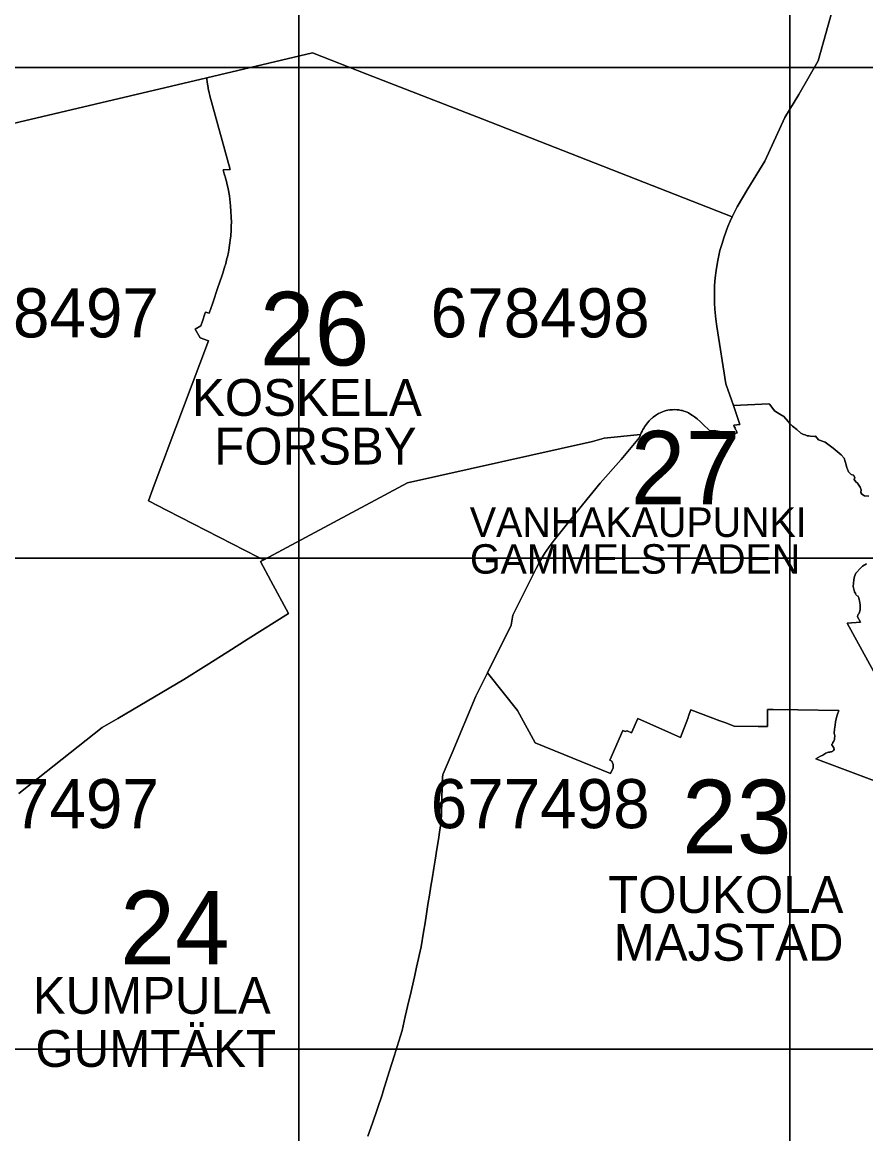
# Model space of a CAD drawing. Extents: x 25485000 to 25520000, y 6656775 to 6690000.
# Drawn here: x 25497436 to 25499155, y 6676827 to 6679092 of the extents above; entities that cross this region are included whole.
import ezdxf

# ---------------------------------------------------------------- set-up
doc = ezdxf.new("R2010")
doc.units = 0
doc.layers.add('Level 63', color=7, linetype='Continuous')

msp = doc.modelspace()

# ---------------------------------------------------------------- linework, layer by layer
at = {"layer": 'Level 63'}
for points in [[(25497000, 6679000), (25498000, 6679000), (25498000, 6680000), (25497000, 6680000)], [(25498000, 6679000), (25499000, 6679000), (25499000, 6680000), (25498000, 6680000)], [(25499000, 6679000), (25500000, 6679000), (25500000, 6680000), (25499000, 6680000)], [(25497693.2, 6678117), (25497731.3, 6678097.5), (25497917.1, 6678002.3), (25497928.4, 6677996.5), (25498221.5, 6678153.3), (25498598.3, 6678238), (25498621.9, 6678244.4), (25498696, 6678251.9), (25498697.5, 6678255.3), (25498699.1, 6678258.6), (25498701, 6678262.2), (25498703.2, 6678265.8), (25498704.5, 6678267.8), (25498706.4, 6678270.6), (25498710.5, 6678276), (25498714, 6678279.9), (25498716, 6678282.1), (25498718.5, 6678284.5), (25498719.8, 6678285.6), (25498722, 6678287.6), (25498726.3, 6678290.7), (25498728.4, 6678292.1), (25498730.6, 6678293.4), (25498732.8, 6678294.7), (25498736, 6678296.3), (25498740.7, 6678298.3), (25498744.2, 6678299.5), (25498748.2, 6678300.7), (25498751.5, 6678301.4), (25498755.9, 6678302.2), (25498761.3, 6678302.7), (25498766.1, 6678302.8), (25498770.8, 6678302.5), (25498774, 6678302.2), (25498776.5, 6678301.8), (25498779.8, 6678301.2), (25498781.6, 6678300.7), (25498784.5, 6678299.9), (25498787.3, 6678298.9), (25498790.9, 6678297.5), (25498793.8, 6678296), (25498796.7, 6678294.3), (25498801.7, 6678291), (25498806.2, 6678288), (25498811.4, 6678283.9), (25498818.2, 6678278), (25498823.1, 6678273.4), (25498837.2, 6678259.3), (25498846.1, 6678260.1), (25498857.3, 6678258), (25498873.7, 6678255), (25498887.6, 6678253.2), (25498893.2, 6678255.4), (25498892.3, 6678257.1), (25498891.8, 6678259.4), (25498891, 6678261.1), (25498889.5, 6678262.5), (25498888.8, 6678263.8), (25498889.3, 6678264.1), (25498887.1, 6678268.7), (25498886.4, 6678271), (25498898.3, 6678272.2), (25498885.2, 6678311), (25498870.2, 6678355.4), (25498851.7, 6678472.3), (25498849.6, 6678487.1), (25498847.5, 6678507.4), (25498846.9, 6678519.5), (25498846.5, 6678531.5), (25498846.7, 6678543.5), (25498847.1, 6678555.4), (25498848.3, 6678571), (25498849.9, 6678586.4), (25498852.1, 6678599.2), (25498853.4, 6678606.8), (25498857.9, 6678626.8), (25498862.1, 6678641.6), (25498865.7, 6678653.1), (25498869.9, 6678664.4), (25498874.1, 6678675.6), (25498878.9, 6678686.7), (25498883.1, 6678695.6), (25498374.4, 6678894.4), (25498138.3, 6678986.6), (25498027.5, 6679029.9), (25497812.2, 6678979.1), (25497812.4, 6678976.1), (25497813, 6678970.5), (25497813.5, 6678966.2), (25497814.2, 6678962.2), (25497814.7, 6678959.4), (25497814.9, 6678957.8), (25497815.2, 6678956.4), (25497815.2, 6678956.3), (25497815.3, 6678956), (25497815.4, 6678955.3), (25497815.7, 6678954), (25497816.8, 6678949), (25497817.8, 6678945.1), (25497818.2, 6678943.7), (25497818.6, 6678942.2), (25497860, 6678792.2), (25497845.3, 6678791.1), (25497847, 6678785.9), (25497847.9, 6678783), (25497848.6, 6678780.9), (25497849.1, 6678778.9), (25497849.5, 6678777.7), (25497850.3, 6678774.7), (25497851.5, 6678770.2), (25497853.1, 6678764), (25497855.7, 6678752.5), (25497858.2, 6678738.6), (25497860.8, 6678718.3), (25497862.3, 6678683.8), (25497862.2, 6678677.8), (25497861.8, 6678668.2), (25497861, 6678656.9), (25497860, 6678647.9), (25497859.4, 6678642.7), (25497858.7, 6678637.6), (25497857, 6678627.9), (25497856.2, 6678623.5), (25497854.2, 6678613.9), (25497853.4, 6678610.6), (25497851.8, 6678603.9), (25497850.2, 6678598), (25497849.3, 6678595.1), (25497844.8, 6678580.6), (25497842.9, 6678575), (25497834.9, 6678551.3), (25497832.8, 6678545.2), (25497826.5, 6678526.7), (25497823.6, 6678518.1), (25497817.2, 6678499.2), (25497809.6, 6678501.7), (25497808.3, 6678498), (25497803.2, 6678482.8), (25497800, 6678473.4), (25497788.7, 6678466.6), (25497798.9, 6678449.4), (25497815.4, 6678443.2), (25497731.6, 6678219.4), (25497728.1, 6678210.1), (25497717.5, 6678181.7), (25497702.3, 6678141.3)], [(25497000, 6678000), (25498000, 6678000), (25498000, 6679000), (25497000, 6679000)], [(25498000, 6678000), (25499000, 6678000), (25499000, 6679000), (25498000, 6679000)], [(25499000, 6678000), (25500000, 6678000), (25500000, 6679000), (25499000, 6679000)], [(25497000, 6677000), (25498000, 6677000), (25498000, 6678000), (25497000, 6678000)], [(25498000, 6677000), (25499000, 6677000), (25499000, 6678000), (25498000, 6678000)], [(25499000, 6677000), (25500000, 6677000), (25500000, 6678000), (25499000, 6678000)], [(25497000, 6676000), (25498000, 6676000), (25498000, 6677000), (25497000, 6677000)], [(25498000, 6676000), (25499000, 6676000), (25499000, 6677000), (25498000, 6677000)], [(25499000, 6676000), (25500000, 6676000), (25500000, 6677000), (25499000, 6677000)]]:
    msp.add_lwpolyline(points, close=True, dxfattribs=at)
for points in [[(25497201, 6678835), (25497812.2, 6678979.1), (25498027.5, 6679029.9), (25498138.3, 6678986.6), (25498374.4, 6678894.4), (25498883.1, 6678695.6), (25498893.3, 6678715.7), (25498914.4, 6678752.7), (25498949.4, 6678808.9), (25498990.1, 6678898.1), (25499018.9, 6678944.9), (25499058.2, 6679013.5), (25499094, 6679142.7)], [(25499094, 6679142.7), (25499058.2, 6679013.5), (25499018.9, 6678944.9), (25498990.1, 6678898.1), (25498949.4, 6678808.9), (25498914.4, 6678752.7), (25498893.3, 6678715.7), (25498883.1, 6678695.6), (25498878.9, 6678686.7), (25498874.1, 6678675.6), (25498869.9, 6678664.4), (25498865.7, 6678653.1), (25498862.1, 6678641.6), (25498857.9, 6678626.8), (25498853.4, 6678606.8), (25498852.1, 6678599.2)], [(25497429.3, 6677520.9), (25497468.6, 6677551.9), (25497599.2, 6677655.1), (25497631.3, 6677673.2), (25497765.3, 6677752.8), (25497811, 6677781.6), (25497855, 6677809.3), (25497896.5, 6677835.5), (25497978.6, 6677887.3), (25497942.8, 6677954.3), (25497922, 6677993.1), (25497928.4, 6677996.5), (25497917.1, 6678002.3), (25497731.3, 6678097.5), (25497693.2, 6678117), (25497702.3, 6678141.3), (25497717.5, 6678181.7), (25497728.1, 6678210.1), (25497731.6, 6678219.4), (25497815.4, 6678443.2), (25497798.9, 6678449.4), (25497788.7, 6678466.6), (25497800, 6678473.4), (25497803.2, 6678482.8), (25497808.3, 6678498), (25497809.6, 6678501.7), (25497817.2, 6678499.2), (25497823.6, 6678518.1), (25497826.5, 6678526.7), (25497832.8, 6678545.2), (25497834.9, 6678551.3), (25497842.9, 6678575), (25497844.8, 6678580.6), (25497849.3, 6678595.1), (25497850.2, 6678598), (25497851.8, 6678603.9), (25497853.4, 6678610.6), (25497854.2, 6678613.9), (25497856.2, 6678623.5), (25497857, 6678627.9), (25497858.7, 6678637.6), (25497859.4, 6678642.7), (25497860, 6678647.9), (25497861, 6678656.9), (25497861.8, 6678668.2), (25497862.2, 6678677.8), (25497862.3, 6678683.8), (25497860.8, 6678718.3), (25497858.2, 6678738.6), (25497855.7, 6678752.5), (25497853.1, 6678764), (25497851.5, 6678770.2), (25497850.3, 6678774.7), (25497849.5, 6678777.7), (25497849.1, 6678778.9), (25497848.6, 6678780.9), (25497847.9, 6678783), (25497847, 6678785.9), (25497845.3, 6678791.1), (25497860, 6678792.2), (25497818.6, 6678942.2), (25497818.2, 6678943.7), (25497817.8, 6678945.1), (25497816.8, 6678949), (25497815.7, 6678954), (25497815.4, 6678955.3), (25497815.3, 6678956), (25497815.2, 6678956.3), (25497815.2, 6678956.4), (25497814.9, 6678957.8), (25497814.7, 6678959.4), (25497814.2, 6678962.2), (25497813.5, 6678966.2), (25497813, 6678970.5), (25497812.4, 6678976.1), (25497812.2, 6678979.1), (25497201, 6678835)], [(25498852.1, 6678599.2), (25498849.9, 6678586.4), (25498848.3, 6678571), (25498847.1, 6678555.4), (25498846.7, 6678543.5), (25498846.5, 6678531.5), (25498846.9, 6678519.5), (25498847.5, 6678507.4), (25498849.6, 6678487.1), (25498851.7, 6678472.3), (25498870.2, 6678355.4), (25498885.2, 6678311), (25498957.2, 6678314.4), (25498959.6, 6678313.1), (25498969, 6678300.2), (25498979.6, 6678293.7), (25498988, 6678288.9), (25498996.7, 6678278.6), (25499000.4, 6678274.7), (25499005.5, 6678268.8), (25499014.3, 6678262.3), (25499023, 6678254.5), (25499028.4, 6678251.9), (25499031.6, 6678251.7), (25499035.7, 6678249.7), (25499038.9, 6678249.6), (25499042.4, 6678248.6), (25499050.5, 6678248), (25499052.9, 6678248.4), (25499058.9, 6678241.2), (25499072.3, 6678236.7), (25499088.3, 6678224), (25499104.6, 6678210.8), (25499111.2, 6678203.8), (25499115.3, 6678190.3), (25499116.4, 6678184.1), (25499117.7, 6678181.8), (25499119.6, 6678176.1), (25499125.6, 6678170.4), (25499130.3, 6678169.2), (25499132.7, 6678164.2), (25499131.1, 6678160.7), (25499134.6, 6678155.7), (25499138.1, 6678152.9), (25499143.9, 6678144.7), (25499145.5, 6678139.5), (25499145.2, 6678134), (25499147, 6678130.7), (25499152.8, 6678127.3), (25499161.5, 6678126.3)], [(25499161.5, 6678126.3), (25499152.8, 6678127.3), (25499147, 6678130.7), (25499145.2, 6678134), (25499145.5, 6678139.5), (25499143.9, 6678144.7), (25499138.1, 6678152.9), (25499134.6, 6678155.7), (25499131.1, 6678160.7), (25499132.7, 6678164.2), (25499130.3, 6678169.2), (25499125.6, 6678170.4), (25499119.6, 6678176.1), (25499117.7, 6678181.8), (25499116.4, 6678184.1), (25499115.3, 6678190.3), (25499111.2, 6678203.8), (25499104.6, 6678210.8), (25499088.3, 6678224), (25499072.3, 6678236.7), (25499058.9, 6678241.2), (25499052.9, 6678248.4), (25499050.5, 6678248), (25499042.4, 6678248.6), (25499038.9, 6678249.6), (25499035.7, 6678249.7), (25499031.6, 6678251.7), (25499028.4, 6678251.9), (25499023, 6678254.5), (25499014.3, 6678262.3), (25499005.5, 6678268.8), (25499000.4, 6678274.7), (25498996.7, 6678278.6), (25498988, 6678288.9), (25498979.6, 6678293.7), (25498969, 6678300.2), (25498959.6, 6678313.1), (25498957.2, 6678314.4), (25498885.2, 6678311), (25498898.3, 6678272.2), (25498886.4, 6678271), (25498887.1, 6678268.7), (25498889.3, 6678264.1), (25498888.8, 6678263.8), (25498889.5, 6678262.5), (25498891, 6678261.1), (25498891.8, 6678259.4), (25498892.3, 6678257.1), (25498893.2, 6678255.4), (25498887.6, 6678253.2), (25498873.7, 6678255), (25498857.3, 6678258), (25498846.1, 6678260.1), (25498837.2, 6678259.3), (25498823.1, 6678273.4), (25498818.2, 6678278), (25498811.4, 6678283.9), (25498806.2, 6678288), (25498801.7, 6678291), (25498796.7, 6678294.3), (25498793.8, 6678296), (25498790.9, 6678297.5), (25498787.3, 6678298.9), (25498784.5, 6678299.9), (25498781.6, 6678300.7), (25498779.8, 6678301.2), (25498776.5, 6678301.8), (25498774, 6678302.2), (25498770.8, 6678302.5), (25498766.1, 6678302.8), (25498761.3, 6678302.7), (25498755.9, 6678302.2), (25498751.5, 6678301.4), (25498748.2, 6678300.7), (25498744.2, 6678299.5), (25498740.7, 6678298.3), (25498736, 6678296.3), (25498732.8, 6678294.7), (25498730.6, 6678293.4), (25498728.4, 6678292.1), (25498726.3, 6678290.7), (25498722, 6678287.6), (25498719.8, 6678285.6), (25498718.5, 6678284.5), (25498716, 6678282.1), (25498714, 6678279.9), (25498710.5, 6678276), (25498706.4, 6678270.6), (25498704.5, 6678267.8), (25498703.2, 6678265.8), (25498701, 6678262.2), (25498699.1, 6678258.6), (25498697.5, 6678255.3), (25498696, 6678251.9), (25498693.8, 6678245.9), (25498656.8, 6678200.9), (25498613.5, 6678153), (25498578.1, 6678108.9), (25498520.4, 6678037), (25498515.9, 6678031.1), (25498509.8, 6678023.2), (25498503.8, 6678014.5), (25498501.7, 6678011.4), (25498490.8, 6677993.4), (25498483.3, 6677979.1), (25498436.2, 6677884.3), (25498432.7, 6677863.9), (25498384.1, 6677766.3), (25498445.5, 6677689.6), (25498481.4, 6677624.1), (25498634.8, 6677561.2), (25498640, 6677573.3), (25498640.1, 6677579.8), (25498637.8, 6677586.5), (25498633.8, 6677588.3), (25498660.2, 6677648.8), (25498664.8, 6677646.8), (25498668.7, 6677648.4), (25498677.8, 6677644.4), (25498690.4, 6677673.2), (25498759.4, 6677643.1), (25498777.7, 6677635.1), (25498792.2, 6677673.4), (25498794.6, 6677680), (25498797.5, 6677687.5), (25498798.9, 6677691.2), (25498857.8, 6677669), (25498868.1, 6677665.1), (25498887.1, 6677658), (25498935.7, 6677657.4), (25498943.7, 6677657.4), (25498954.7, 6677657.2), (25498955.1, 6677691.7), (25498960.1, 6677691.7), (25498966.1, 6677691.6), (25499016.7, 6677691), (25499099.9, 6677690.1), (25499096.6, 6677680.6), (25499095.6, 6677675.4), (25499093.3, 6677666.7), (25499092.8, 6677659.7), (25499091.3, 6677651.7), (25499090.8, 6677643.6), (25499091.8, 6677638.5), (25499091.6, 6677633), (25499091.2, 6677630.6), (25499090, 6677627.5), (25499088.2, 6677624.4), (25499087.6, 6677623.2), (25499086.2, 6677621.2), (25499086.2, 6677619.8), (25499088.5, 6677615.5), (25499089.9, 6677613.6), (25499090.8, 6677610.6), (25499089.5, 6677608), (25499087.9, 6677606.6), (25499085.3, 6677605.4), (25499083.5, 6677605.3), (25499081.5, 6677604.8), (25499078.9, 6677604.8), (25499076.9, 6677604.4), (25499073.6, 6677602.8), (25499067.4, 6677599), (25499062.7, 6677596.8), (25499053.2, 6677591.3), (25499324.7, 6677489.2)], [(25498140.1, 6676822.7), (25498149.9, 6676849), (25498169.4, 6676906.6), (25498171.8, 6676914.2), (25498183.9, 6676953.3), (25498194.5, 6676987.6), (25498196.7, 6676994.5), (25498210.2, 6677038.1), (25498216.6, 6677066.2), (25498224, 6677098.4), (25498226.5, 6677108.7), (25498235.2, 6677147.4), (25498239.7, 6677166.9), (25498249.2, 6677208.4), (25498253.9, 6677238.2), (25498256.9, 6677256.9), (25498259.9, 6677275.7), (25498262.9, 6677294.4), (25498266, 6677313.2), (25498269, 6677332), (25498271.3, 6677346.8), (25498274.9, 6677368.8), (25498277.5, 6677385.1), (25498281, 6677407.1), (25498284.2, 6677426.8), (25498287.3, 6677446.6), (25498289.7, 6677461.3), (25498291, 6677503.7), (25498292.1, 6677540.9), (25498292.5, 6677553.7), (25498292.6, 6677555.4), (25498292.9, 6677557.2), (25498293.4, 6677559.1), (25498294.1, 6677560.9), (25498312.1, 6677603.7), (25498360.7, 6677719.2), (25498384.1, 6677766.3), (25498432.7, 6677863.9), (25498436.2, 6677884.3), (25498483.3, 6677979.1), (25498490.8, 6677993.4), (25498501.7, 6678011.4), (25498503.8, 6678014.5), (25498509.8, 6678023.2), (25498515.9, 6678031.1), (25498520.4, 6678037), (25498578.1, 6678108.9), (25498613.5, 6678153), (25498656.8, 6678200.9), (25498693.8, 6678245.9), (25498696, 6678251.9), (25498621.9, 6678244.4), (25498598.3, 6678238), (25498221.5, 6678153.3), (25497928.4, 6677996.5), (25497922, 6677993.1), (25497942.8, 6677954.3), (25497978.6, 6677887.3), (25497896.5, 6677835.5), (25497855, 6677809.3), (25497811, 6677781.6), (25497765.3, 6677752.8), (25497631.3, 6677673.2), (25497599.2, 6677655.1), (25497468.6, 6677551.9), (25497429.3, 6677520.9)], [(25499231.7, 6677658.5), (25499116.9, 6677867.7), (25499144.1, 6677869.8), (25499138, 6677880.7), (25499139, 6677884.5), (25499140.7, 6677886.9), (25499142.1, 6677890), (25499143.3, 6677894.6), (25499143.5, 6677905), (25499142.9, 6677909.1), (25499142, 6677912.9), (25499141.5, 6677916.2), (25499140.9, 6677919.6), (25499139.8, 6677922), (25499138.7, 6677923.4), (25499138, 6677922.9), (25499134.1, 6677927.1), (25499134.5, 6677927.8), (25499132, 6677931.6), (25499129.2, 6677942.3), (25499130.6, 6677956.2), (25499132.3, 6677962.8), (25499134.9, 6677969.6), (25499144.9, 6677980.7), (25499148.5, 6677983.6), (25499156.8, 6677988.8)], [(25499156.8, 6677988.8), (25499148.5, 6677983.6), (25499144.9, 6677980.7), (25499134.9, 6677969.6), (25499132.3, 6677962.8), (25499130.6, 6677956.2), (25499129.2, 6677942.3), (25499132, 6677931.6), (25499134.5, 6677927.8), (25499134.1, 6677927.1), (25499138, 6677922.9), (25499138.7, 6677923.4), (25499139.8, 6677922), (25499140.9, 6677919.6), (25499141.5, 6677916.2), (25499142, 6677912.9), (25499142.9, 6677909.1), (25499143.5, 6677905), (25499143.3, 6677894.6), (25499142.1, 6677890), (25499140.7, 6677886.9), (25499139, 6677884.5), (25499138, 6677880.7), (25499144.1, 6677869.8), (25499116.9, 6677867.7), (25499231.7, 6677658.5)], [(25499324.7, 6677489.2), (25499053.2, 6677591.3), (25499062.7, 6677596.8), (25499067.4, 6677599), (25499073.6, 6677602.8), (25499076.9, 6677604.4), (25499078.9, 6677604.8), (25499081.5, 6677604.8), (25499083.5, 6677605.3), (25499085.3, 6677605.4), (25499087.9, 6677606.6), (25499089.5, 6677608), (25499090.8, 6677610.6), (25499089.9, 6677613.6), (25499088.5, 6677615.5), (25499086.2, 6677619.8), (25499086.2, 6677621.2), (25499087.6, 6677623.2), (25499088.2, 6677624.4), (25499090, 6677627.5), (25499091.2, 6677630.6), (25499091.6, 6677633), (25499091.8, 6677638.5), (25499090.8, 6677643.6), (25499091.3, 6677651.7), (25499092.8, 6677659.7), (25499093.3, 6677666.7), (25499095.6, 6677675.4), (25499096.6, 6677680.6), (25499099.9, 6677690.1), (25499016.7, 6677691), (25498966.1, 6677691.6), (25498960.1, 6677691.7), (25498955.1, 6677691.7), (25498954.7, 6677657.2), (25498943.7, 6677657.4), (25498935.7, 6677657.4), (25498887.1, 6677658), (25498868.1, 6677665.1), (25498857.8, 6677669), (25498798.9, 6677691.2), (25498797.5, 6677687.5), (25498794.6, 6677680), (25498792.2, 6677673.4), (25498777.7, 6677635.1), (25498759.4, 6677643.1), (25498690.4, 6677673.2), (25498677.8, 6677644.4), (25498668.7, 6677648.4), (25498664.8, 6677646.8), (25498660.2, 6677648.8), (25498633.8, 6677588.3), (25498637.8, 6677586.5), (25498640.1, 6677579.8), (25498640, 6677573.3), (25498634.8, 6677561.2), (25498481.4, 6677624.1), (25498445.5, 6677689.6), (25498384.1, 6677766.3), (25498360.7, 6677719.2), (25498312.1, 6677603.7), (25498294.1, 6677560.9), (25498293.4, 6677559.1), (25498292.9, 6677557.2), (25498292.6, 6677555.4), (25498292.5, 6677553.7), (25498292.1, 6677540.9), (25498291, 6677503.7), (25498289.7, 6677461.3), (25498287.3, 6677446.6), (25498284.2, 6677426.8), (25498281, 6677407.1), (25498277.5, 6677385.1), (25498274.9, 6677368.8), (25498271.3, 6677346.8), (25498269, 6677332), (25498266, 6677313.2), (25498262.9, 6677294.4), (25498259.9, 6677275.7), (25498256.9, 6677256.9), (25498253.9, 6677238.2), (25498249.2, 6677208.4), (25498239.7, 6677166.9), (25498235.2, 6677147.4), (25498226.5, 6677108.7), (25498224, 6677098.4), (25498216.6, 6677066.2), (25498210.2, 6677038.1), (25498196.7, 6676994.5), (25498194.5, 6676987.6), (25498183.9, 6676953.3), (25498171.8, 6676914.2), (25498169.4, 6676906.6), (25498149.9, 6676849), (25498140.1, 6676822.7)]]:
    msp.add_lwpolyline(points, dxfattribs=at)

# ---------------------------------------------------------------- texts
for s, height, p in [('678497', 100, (25497268.5, 6678450)), ('26', 150, (25497920.3, 6678392.8)), ('678498', 100, (25498268.5, 6678450)), ('KOSKELA', 75, (25497782.1, 6678290.1)), ('FORSBY', 75, (25497827.3, 6678190.9)), ('27', 150, (25498676.1, 6678109.5)), ('VANHAKAUPUNKI', 60, (25498348.2, 6678043.4)), ('GAMMELSTADEN', 60, (25498348.4, 6677968.6)), ('677497', 100, (25497268.5, 6677450)), ('677498', 100, (25498268.5, 6677450)), ('23', 150, (25498780.7, 6677398.7)), ('TOUKOLA', 75, (25498630.2, 6677277.3)), ('24', 150, (25497635.8, 6677172.3)), ('MAJSTAD', 75, (25498641.5, 6677179.9)), ('KUMPULA', 75, (25497457.7, 6677071.8)), ('GUMTÄKT', 75, (25497463, 6676963.6))]:
    msp.add_text(s, height=height, dxfattribs=at).set_placement(p)

doc.saveas('drawing.dxf')
